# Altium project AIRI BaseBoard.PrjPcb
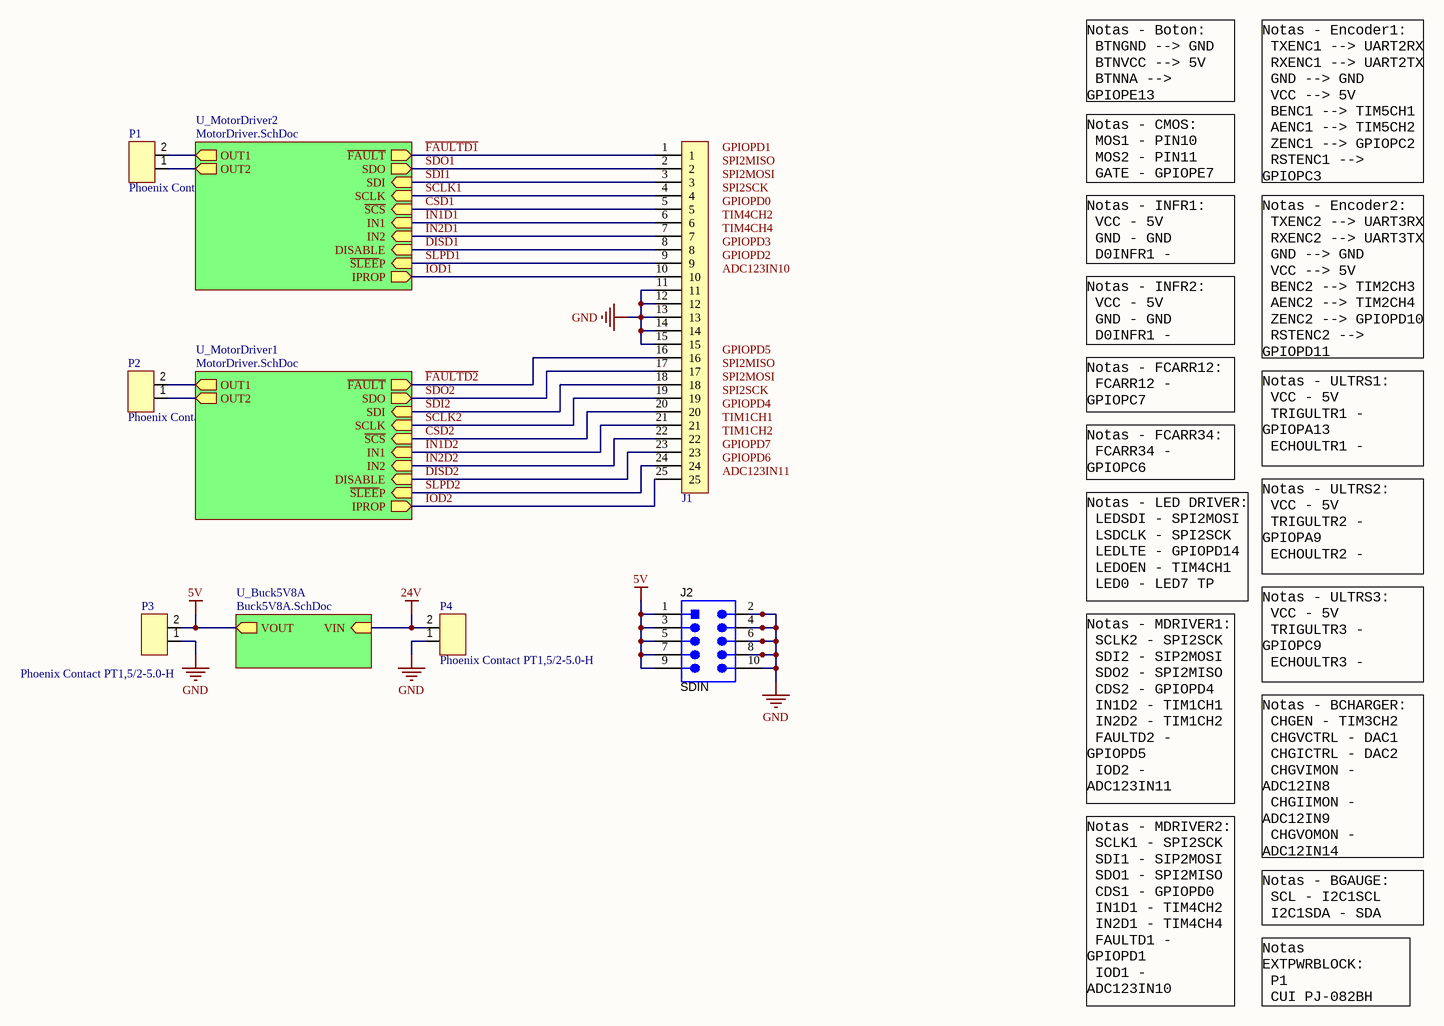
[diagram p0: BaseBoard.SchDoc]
3 sheets, 47 parts. Net scope: hierarchical (ports join the sheet entries above them; power ports are global).
Sheets:
  BaseBoard.SchDoc
    U_Buck5V8A = Buck5V8A.SchDoc
    U_MotorDriver2 = MotorDriver.SchDoc
    U_MotorDriver1 = MotorDriver.SchDoc

## Sheet BaseBoard.SchDoc
size A3; DocumentNumber: 1; SheetNumber: 1; SheetTotal: 9

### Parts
J1  Sullins PREC025SAAN-RC  [PCB-ss9uik38su1ryg1jck95-1]  (value not drawn)
J2  SDIN  [PCB-38ol6r0j9lzrfjjpfgyz-1]
P1  Phoenix Contact PT1,5/2-5.0-H  [PCB-uxxh2nr7ib8r5ep0eqej-1]
P2  Phoenix Contact PT1,5/2-5.0-H  [PCB-uxxh2nr7ib8r5ep0eqej-1]
P3  Phoenix Contact PT1,5/2-5.0-H  [PCB-uxxh2nr7ib8r5ep0eqej-1]
P4  Phoenix Contact PT1,5/2-5.0-H  [PCB-uxxh2nr7ib8r5ep0eqej-1]

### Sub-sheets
U_Buck5V8A = Buck5V8A.SchDoc: VOUT (out), VIN (in)
U_MotorDriver1 = MotorDriver.SchDoc: OUT1 (out), OUT2 (out), IPROP (out), SDO, ~{FAULT} (out), SDI (in), SCLK (in), ~{SCS} (in), ~{SLEE}P (in), DISABLE (in), IN2 (in), IN1 (in)
U_MotorDriver2 = MotorDriver.SchDoc: OUT1 (out), OUT2 (out), IPROP (out), SDO (out), ~{FAULT} (out), SDI (in), SCLK (in), ~{SCS} (in), ~{SLEE}P (in), DISABLE (in), IN2 (in), IN1 (in)

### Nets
5V: J2.1 J2.3 J2.5 J2.7 J2.9 P3.2 ; sheet U_Buck5V8A/VOUT
24V: P4.2 ; sheet U_Buck5V8A/VIN
GND: J1.11 J1.12 J1.13 J1.14 J1.15 J2.2 J2.4 J2.6 J2.8 J2.10 P3.1 P4.1
~{CSD1}: J1.5 ; sheet U_MotorDriver2/~{SCS}
~{CSD2}: J1.20 ; sheet U_MotorDriver1/~{SCS}
DISD1: J1.8 ; sheet U_MotorDriver2/DISABLE
DISD2: J1.23 ; sheet U_MotorDriver1/DISABLE
~{FAULTD1}: J1.1 ; sheet U_MotorDriver2/~{FAULT}
~{FAULTD2}: J1.16 ; sheet U_MotorDriver1/~{FAULT}
IN1D1: J1.6 ; sheet U_MotorDriver2/IN1
IN1D2: J1.21 ; sheet U_MotorDriver1/IN1
IN2D1: J1.7 ; sheet U_MotorDriver2/IN2
IN2D2: J1.22 ; sheet U_MotorDriver1/IN2
IOD1: J1.10 ; sheet U_MotorDriver2/IPROP
IOD2: J1.25 ; sheet U_MotorDriver1/IPROP
~{SLPD1}: J1.9 ; sheet U_MotorDriver2/~{SLEE}P
~{SLPD2}: J1.24 ; sheet U_MotorDriver1/~{SLEE}P
SCLK1: J1.4 ; sheet U_MotorDriver2/SCLK
SCLK2: J1.19 ; sheet U_MotorDriver1/SCLK
SDI1: J1.3 ; sheet U_MotorDriver2/SDI
SDI2: J1.18 ; sheet U_MotorDriver1/SDI
SDO1: J1.2 ; sheet U_MotorDriver2/SDO
SDO2: J1.17 ; sheet U_MotorDriver1/SDO
NetP1_1: P1.1 ; sheet U_MotorDriver2/OUT2
NetP1_2: P1.2 ; sheet U_MotorDriver2/OUT1
NetP2_1: P2.1 ; sheet U_MotorDriver1/OUT2
NetP2_2: P2.2 ; sheet U_MotorDriver1/OUT1

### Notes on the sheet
- Notas - Boton:
  BTNGND --> GND
  BTNVCC --> 5V
  BTNNA --> GPIOPE13
  BTNCMN --> 3.3V
- Notas - CMOS:
  MOS1 - PIN10
  MOS2 - PIN11
  GATE - GPIOPE7
- Notas - Encoder1:
  TXENC1 --> UART2RX
  RXENC1 --> UART2TX
  GND --> GND
  VCC --> 5V
  BENC1 --> TIM5CH1
  AENC1 --> TIM5CH2
  ZENC1 --> GPIOPC2
  RSTENC1 --> GPIOPC3
- Notas - INFR1:
  VCC - 5V
  GND - GND
  D0INFR1 - GPIOPA15
- Notas - INFR2:
  VCC - 5V
  GND - GND
  D0INFR1 - GPIOPA14
- Notas - Encoder2:
  TXENC2 --> UART3RX
  RXENC2 --> UART3TX
  GND --> GND
  VCC --> 5V
  BENC2 --> TIM2CH3
  AENC2 --> TIM2CH4
  ZENC2 --> GPIOPD10
  RSTENC2 --> GPIOPD11
- Notas - FCARR12:
  FCARR12 - GPIOPC7
  GND - GND
- Notas - ULTRS1:
  VCC - 5V
  TRIGULTR1 - GPIOPA13
  ECHOULTR1 - GPIOPA10
  GND - GND
- Notas - FCARR34:
  FCARR34 - GPIOPC6
  GND - GND
- Notas - LED DRIVER:
  LEDSDI - SPI2MOSI
  LSDCLK - SPI2SCK
  LEDLTE - GPIOPD14
  LEDOEN - TIM4CH1
  LED0 - LED7 TP
- Notas - ULTRS2:
  VCC - 5V
  TRIGULTR2 - GPIOPA9
  ECHOULTR2 - GPIOPA8
  GND - GND
- Notas - ULTRS3:
  VCC - 5V
  TRIGULTR3 - GPIOPC9
  ECHOULTR3 - GPIOPC8
  GND - GND
- Notas - MDRIVER1:
  SCLK2 - SPI2SCK
  SDI2 - SIP2MOSI
  SDO2 - SPI2MISO
  CDS2 - GPIOPD4
  IN1D2 - TIM1CH1
  IN2D2 - TIM1CH2
  FAULTD2 - GPIOPD5
  IOD2 - ADC123IN11
  SLPD2 - GPIOPD6
  DISD2 - GPIOPD7
- Notas - BCHARGER:
  CHGEN - TIM3CH2
  CHGVCTRL - DAC1
  CHGICTRL - DAC2
  CHGVIMON - ADC12IN8
  CHGIIMON - ADC12IN9
  CHGVOMON - ADC12IN14
  CHGIOMON - ADC12IN15
  CHGFAULT - GPIOPA6
- Notas - BGAUGE:
  SCL - I2C1SCL
  I2C1SDA - SDA
- Notas - MDRIVER2:
  SCLK1 - SPI2SCK
  SDI1 - SIP2MOSI
  SDO1 - SPI2MISO
  CDS1 - GPIOPD0
  IN1D1 - TIM4CH2
  IN2D1 - TIM4CH4
  FAULTD1 - GPIOPD1
  IOD1 - ADC123IN10
  SLPD1 - GPIOPD2
  DISD1 - GPIOPD3
- Notas EXTPWRBLOCK:
  P1
  CUI PJ-082BH
- Labels drawn without touching a wire or pin: ADC123IN10, ADC123IN11, GPIOPD0, GPIOPD1, GPIOPD2, GPIOPD3, GPIOPD4, GPIOPD5, GPIOPD6, GPIOPD7, SPI2MISO, SPI2MOSI, SPI2SCK, TIM1CH1, TIM1CH2, TIM4CH2, TIM4CH4

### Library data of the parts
J1 = CMP-10abd8f28bd1cf6c-1: Conn Header Vert 25POS 2.54MM
J2 = CMP-eeb327bddb303174-2: Male, 10C, Straight, .100CC; 5.84mm Head/3.05mm Tail, Gold; PBT Phos Bronze, 125 C; Manufacturer Part Number: PBC05DAAN; Number of Positions: 10; Pin Pitch: 2.54 mm
P1-P4 = CMP-29d3e01a948df614-2: TERM BLK, PCB, SCREW, 5.0MM, 2WAY; Connector Type: Terminal Block, PCB; Series: PT 1.5; Connector Mounting: PCB; Pitc...

## Sheet Buck5V8A.SchDoc
size A; DocumentNumber: 3; SheetNumber: 3; SheetTotal: 9
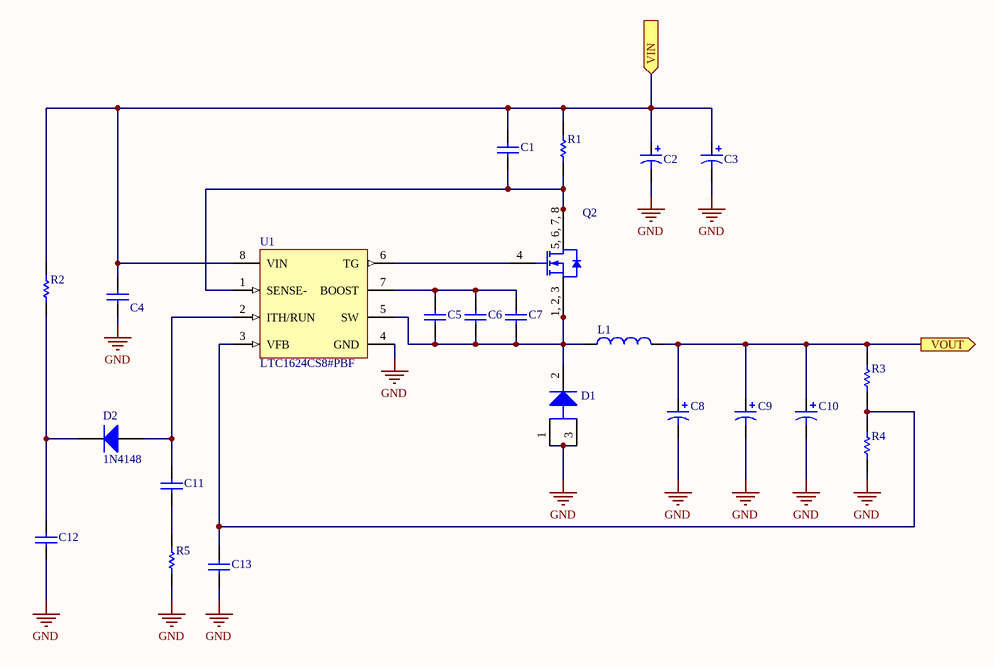
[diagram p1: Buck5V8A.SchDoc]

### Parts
C1  KEMET C0805C102J5HACAUTO  [C0805]  (value not drawn)
C2  Panasonic EEH-ZK1V331P  [Panasonic Series ZK Type V Size G]  (value not drawn)
C3  Panasonic EEH-ZK1V331P  [Panasonic Series ZK Type V Size G]  (value not drawn)
C4  Murata GCD21BR71H104KA01L  [PCB-ssva2zk340p4bh5zvq6f-1]  (value not drawn)
C5  Murata GCD21BR71H104KA01L  [PCB-ssva2zk340p4bh5zvq6f-1]  (value not drawn)
C6  Murata GCD21BR71H104KA01L  [PCB-ssva2zk340p4bh5zvq6f-1]  (value not drawn)
C7  Murata GCD21BR71H104KA01L  [PCB-ssva2zk340p4bh5zvq6f-1]  (value not drawn)
C8  Panasonic EEE-FT1C102AP  [PCB-xaiyb7r7dwp27xp9tfwa-1]  (value not drawn)
C9  Panasonic EEE-FT1C102AP  [PCB-xaiyb7r7dwp27xp9tfwa-1]  (value not drawn)
C10  Panasonic 16SVPE180M  [PCB-ae1oimqhkk0yeik3kf6i-1]  (value not drawn)
C11  KEMET C0805C102J5HACAUTO  [C0805]  (value not drawn)
C12  Murata GCM21BR71H104KA37L  [C0805]  (value not drawn)
C13  Kemet C0805C101J5GAC7800  [C0805]  (value not drawn)
D1  MBRB1645T4G  [HTD2PAK]  (value not drawn)
D2  1N4148  [SODFL250X100-2M]
L1  Bourns SRP1770C-470M  [SRP1770C]  (value not drawn)
Q2  Infineon IRF7470TRPBF  [SOIC8]  (value not drawn)
R1  Yageo PE1206FRF7W0R012L  [PF1206]  (value not drawn)
R2  Yageo RC0805FR-071ML  [PCB-lzr0fin07yxsgk684m62-1]  (value not drawn)
R3  Yageo RC0805FR-0718KL  [RESC2013X60X35ML10T20]  (value not drawn)
R4  Yageo RC0805FR-075K6L  [RC0805FR]  (value not drawn)
R5  Yageo RC0805FR-075K6L  [RC0805FR]  (value not drawn)
U1  LTC1624CS8#PBF  [LT-S8-8_L]

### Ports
VIN (in), VOUT (out)

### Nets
5V: C8.1 C9.1 C10.1 L1.2 R3.2 ; port VOUT
24V: C1.2 C2.1 C3.1 C4.1 R1.2 R2.2 U1.8(VIN) ; port VIN
GND: C2.2 C3.2 C4.2 C8.2 C9.2 C10.2 C12.1 C13.1 D1.1(A) D1.3(A) R4.1 R5.1 U1.4(GND)
NetC1_1: C1.1 Q2.5(D) Q2.6(D) Q2.7(D) Q2.8(D) R1.1 U1.1(SENSE-)
NetC5_1: C5.1 C6.2 C7.1 D1.2(K) L1.1 Q2.1(S) Q2.2(S) Q2.3(S) U1.5(SW)
NetC5_2: C5.2 C6.1 C7.2 U1.7(BOOST)
NetC11_1: C11.1 R5.2
NetC11_2: C11.2 D2.1(A) U1.2(ITH/RUN)
NetC12_2: C12.2 D2.2(K) R2.1
NetC13_2: C13.2 R3.1 R4.2 U1.3(VFB)
NetQ2_4: Q2.4(G) U1.6(TG)

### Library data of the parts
C1 C11 = CMP-4c3f800f43c993f8-1: Cap Ceramic 0.001uF 50V X8R 5% Pad SMD 0805 150C Automotive T/R; Capacitance: 1.00 nF; Lead-Free Status: Lead Free; Voltage Rating (DC): 50.0 V
C2 C3 = CMP-bfb3722bbd176074-3: EEH ZK (V) Series 35 V 330 uF 105°C 10x10.2 mm SMT Hybrid Aluminum Polymer
C4-C7 = CMP-5b5d9311dba3849a-1: Cap Ceramic 0.1uF 50V X7R 10% Pad SMD 0805 125C Automotive T/R; Capacitance: 100 nF; Voltage Rating (DC): 50.0 V
C8 C9 = CMP-36c9fe878397e90e-7: Cap Aluminum Lytic 1000uF 16V 20% (10.5 X 10.0mm) SMD 0.06 Ohm 1190mA 2000h 105?C Automotive T/R; Lead-Free Status: Lead Free; Voltage Rating (DC): 16.0 V; Equivalent Series Resistance (ESR): 60 mΩ; Capacitance: 1000 µF
C10 = CMP-11222308-5: Cap Aluminum 180uF 16V 20% (6.3 X 9.9mm) Cylindrical 4460mA 2000hr 105°C T/R; Voltage Rating (DC): 16.0 V; Equivalent Series Resistance (ESR): 0.011 Ω; Capacitance: 0.00018 F; Lead-Free Status: Lead Free
C12 = CMP-135114-3: Cap Ceramic 0.1uF 50V X7R 10% SMD 0805 125C Embossed T/R; Capacitance: 1e-07 F; Lead-Free Status: Lead Free; Voltage Rating (DC): 50.0 V
C13 = CMP-8262039-4: Multilayer Ceramic Capacitors MLCC - SMD/SMT 50volts 100pF C0G 5%; Manufacturer Part Number: C0805C101J5GACTU; Capacitance: 1e-10 F; Lead-Free Status: Lead Free; Voltage Rating (DC): 50.0 V
D1 = CMP-822676-10: SWITCHMODE(TM) Power Rectifier, 45 V, 3-Pin D2PAK, Pb-Free, Tube
D2 = CMP-814637-10: Small Signal Diode, 75 V, 0.15 A, -55 to 150 degC, 2-Pin SOD-323, RoHS, Tape and Reel
L1 = CMP-e4132b39041c3bd4-1: Inductor Power Shielded 47uH 20% 8.7A 7MHz 2-Pin Surface Mount T/R
Q2 = CMP-983352d49b9a47f4-3: Mosfet, Power; N-ch; Vdss 40V; Rds(on) 9 Milliohms; Id 10A; SO-8; Pd 2.5W; Vgs +/-12V; Current Rating: 11.0 A; Lead-Free Status: Lead Free; Voltage Rating (DC): 40.0 V; Breakdown Voltage (Drain to Source): 40.0 V (min); Drain to Source Resistance (on) (Rds): 9.00 m?; Polarity: N-Channel; Rise Time: 1.90 ns; Continuous Drain Current (Ids): 11.0 A, 10.0 A; Power Dissipation: 2.50 W
R1 = CMP-ed1a2051f20e32dd-1: Res Current Sense Metal Foil 1206 12m Ohms 1% 1/2W ±100ppm/°C Molded SMD Paper T/R; Resistance: 12.0 m?
R2 = CMP-c7f10c99c5f61836-7: Res Thick Film 0805 1M Ohm 1% 0.125W(1/8W) ±100ppm/C Pad SMD T/R; Case/Package (SI): 2012; Lead-Free Status: Lead Free; Power Rating: 125 mW; Resistance: 1.00 M?; Temperature Coefficient: -100 ppm/°C to 100 ppm/°C; Voltage Rating (DC): 150 V
R3 = CMP-1875592-5: YAGEO (PHYCOMP)   RC0805FR-0718KL   RESISTOR, RC12H 0805 18K; Resistance Tolerance: ±1%; Power Rating: 0.125 W; Lead-Free Status: Lead Free; Voltage Rating (DC): 150.0 V; Case/Package (SI): 2012; Resistance: 18000.0 Ω
R4 R5 = CMP-5c9997e7c49d835e-2: Res Thick Film 0805 5.6K Ohm 1% 0.125W(1/8W) ±100ppm/C Pad SMD T/R; Power Rating: 125 mW; Case/Package (SI): 2012; Voltage Rating (DC): 150 V; Resistance: 5.60 k?; Temperature Coefficient: -100 ppm/°C to 100 ppm/°C; Lead-Free Status: Lead Free
U1 = CMP-1475384-2: High Efficiency N-Channel Switching Regulator Controller, 8-pin SOIC (S8-8), 0 to 70 degC, Pb-Free; Frequency: 225000.0 Hz; Lead-Free Status: Lead Free; Number of Outputs: 1; Output Current: 10.0 A; Output Voltage: 30.0 V

## Sheet MotorDriver.SchDoc
size A; DocumentNumber: 4; SheetNumber: 4; SheetTotal: 9
Used 2 times, as channels U_MotorDriver2, U_MotorDriver1. Parts and nets are listed once, with the designators drawn on the sheet.
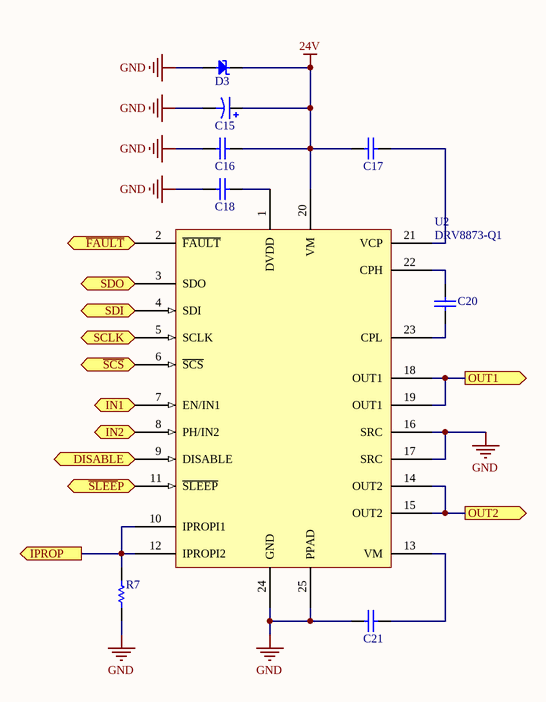
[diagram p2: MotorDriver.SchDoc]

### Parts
C15  Panasonic EEE-HA1V101XP  [PCB-yncmx9jt7av7ibwhpkx7-1]  (value not drawn)
C16  Murata GCD21BR71H104KA01L  [PCB-ssva2zk340p4bh5zvq6f-1]  (value not drawn)
C17  Murata GCM21BR71H105KA03L  [CAPC2013X140X45ML15T25]  (value not drawn)
C18  Murata GCM21BR71H105KA03L  [CAPC2013X140X45ML15T25]  (value not drawn)
C20  Murata GCE21BR71H473KA01L  [PCB-vdoll2pl29m8ltnc4a0p-1]  (value not drawn)
C21  Murata GCD21BR71H104KA01L  [PCB-ssva2zk340p4bh5zvq6f-1]  (value not drawn)
D3  SMBJ28A  [PCB-c143qqmc0v6vbhfo61i0-1]  (value not drawn)
R7  Yageo RC0805FR-07820RL  [PCB-tlec0rbgb5i2w1be04n0-1]  (value not drawn)
U2  DRV8873-Q1  [HTSSOP-24]

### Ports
DISABLE (in), IN1 (in), IN2 (in), IPROP (out), OUT1 (out), OUT2 (out), SCLK (in), SDI (in), SDO (out), ~{FAULT} (out), ~{SCS} (in), ~{SLEE}P (in)

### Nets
24V: C15.1 C16.1 C17.2 D3.1(K) U2.20(VM)
GND: C15.2 C16.2 C18.2 C21.2 D3.2(A) R7.1 U2.16(SRC) U2.17(SRC) U2.24(GND) U2.25(PPAD)
DISABLE: U2.9(DISABLE) ; port DISABLE
~{FAULT}: U2.2(~{FAULT}) ; port ~{FAULT}
IN1: U2.7(EN/IN1) ; port IN1
IN2: U2.8(PH/IN2) ; port IN2
IPROP: R7.2 U2.10(IPROPI1) U2.12(IPROPI2) ; port IPROP
OUT1: U2.18(OUT1) U2.19(OUT1) ; port OUT1
OUT2: U2.14(OUT2) U2.15(OUT2) ; port OUT2
~{SCS}: U2.6(~{SCS}) ; port ~{SCS}
~{SLEE}P: U2.11(~{SLEEP}) ; port ~{SLEE}P
SCLK: U2.5(SCLK) ; port SCLK
SDI: U2.4(SDI) ; port SDI
SDO: U2.3(SDO) ; port SDO
NetC17_1: C17.1 U2.21(VCP)
NetC18_1: C18.1 U2.1(DVDD)
NetC20_1: C20.1 U2.23(CPL)
NetC20_2: C20.2 U2.22(CPH)
NetC21_1: C21.1 U2.13(VM)

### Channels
U_MotorDriver2: designators end in _$ChannelName#1; ports DISABLE=DISD1 IN1=IN1D1 IN2=IN2D1 IPROP=IOD1 OUT1=NetP1_2 OUT2=NetP1_1 SCLK=SCLK1 SDI=SDI1 SDO=SDO1 ~{FAULT}=~{FAULTD1} ~{SCS}=~{CSD1} ~{SLEE}P=~{SLPD1}
U_MotorDriver1: designators end in _$ChannelName#2; ports DISABLE=DISD2 IN1=IN1D2 IN2=IN2D2 IPROP=IOD2 OUT1=NetP2_2 OUT2=NetP2_1 SCLK=SCLK2 SDI=SDI2 SDO=SDO2 ~{FAULT}=~{FAULTD2} ~{SCS}=~{CSD2} ~{SLEE}P=~{SLPD2}

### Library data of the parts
C15 = CMP-2d6fe63f67daf2a8-1: Electrolytic capacitor SMD 100 µF 35 V 20 % (Ø) 6.3 mm Panasonic EEE-HA1V101XP 1 pc(s); Lead-Free Status: Lead Free
C16 C21 = CMP-5b5d9311dba3849a-1: as C4 on sheet Buck5V8A
C17 C18 = CMP-9133247-2: Cap Ceramic 1uF 50V X7R 10% SMD 0805 125C Embossed T/R; Capacitance: 1e-06 F; Lead-Free Status: Lead Free; Voltage Rating (DC): 50.0 V
C20 = CMP-0103c9dfcdd1dec4-1: Cap Ceramic 0.047uF 50V X7R 10% SMD 0805 125°C Embossed Plastic T/R
D3 = CMP-ea40234f95603587-2: Transient Voltage Suppressor, TVS, SMBJ Series, Unidirectional, 28 V, DO-214AA, 2, 31.1 V; Operating Voltage: 28.0 V; Power Rating: 600 W
R7 = CMP-d46c1f1e7e700bab-2: Surface Mount Thick Film Resistor, RC Series, 820 ohm, 125 mW, - 1%, 150 V, 0805 [2012 Metric]; Lead-Free Status: Lead Free; Case/Package (SI): 2012; Power Rating: 125 mW; Resistance: 820 ?; Voltage Rating (DC): 150 V
U2 = CMP-9df0515b45cc4237-8: Automotive H-bridge motor driver with integrated current sensing and current sense output 24-HTSSOP -40 to 125

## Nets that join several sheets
5V: BaseBoard (6 pins), Buck5V8A (5 pins)
24V: BaseBoard (P4.2), Buck5V8A (7 pins), U_MotorDriver2 (5 pins), U_MotorDriver1 (5 pins)
GND: BaseBoard (12 pins), Buck5V8A (13 pins), U_MotorDriver2 (10 pins), U_MotorDriver1 (10 pins)
~{CSD1}: BaseBoard (J1.5), U_MotorDriver2 (U2_$ChannelName#1.6)
~{CSD2}: BaseBoard (J1.20), U_MotorDriver1 (U2_$ChannelName#2.6)
DISD1: BaseBoard (J1.8), U_MotorDriver2 (U2_$ChannelName#1.9)
DISD2: BaseBoard (J1.23), U_MotorDriver1 (U2_$ChannelName#2.9)
~{FAULTD1}: BaseBoard (J1.1), U_MotorDriver2 (U2_$ChannelName#1.2)
~{FAULTD2}: BaseBoard (J1.16), U_MotorDriver1 (U2_$ChannelName#2.2)
IN1D1: BaseBoard (J1.6), U_MotorDriver2 (U2_$ChannelName#1.7)
IN1D2: BaseBoard (J1.21), U_MotorDriver1 (U2_$ChannelName#2.7)
IN2D1: BaseBoard (J1.7), U_MotorDriver2 (U2_$ChannelName#1.8)
IN2D2: BaseBoard (J1.22), U_MotorDriver1 (U2_$ChannelName#2.8)
IOD1: BaseBoard (J1.10), U_MotorDriver2 (R7_$ChannelName#1.2 U2_$ChannelName#1.10 U2_$ChannelName#1.12)
IOD2: BaseBoard (J1.25), U_MotorDriver1 (R7_$ChannelName#2.2 U2_$ChannelName#2.10 U2_$ChannelName#2.12)
NetP1_1: BaseBoard (P1.1), U_MotorDriver2 (U2_$ChannelName#1.14 U2_$ChannelName#1.15)
NetP1_2: BaseBoard (P1.2), U_MotorDriver2 (U2_$ChannelName#1.18 U2_$ChannelName#1.19)
NetP2_1: BaseBoard (P2.1), U_MotorDriver1 (U2_$ChannelName#2.14 U2_$ChannelName#2.15)
NetP2_2: BaseBoard (P2.2), U_MotorDriver1 (U2_$ChannelName#2.18 U2_$ChannelName#2.19)
~{SLPD1}: BaseBoard (J1.9), U_MotorDriver2 (U2_$ChannelName#1.11)
~{SLPD2}: BaseBoard (J1.24), U_MotorDriver1 (U2_$ChannelName#2.11)
SCLK1: BaseBoard (J1.4), U_MotorDriver2 (U2_$ChannelName#1.5)
SCLK2: BaseBoard (J1.19), U_MotorDriver1 (U2_$ChannelName#2.5)
SDI1: BaseBoard (J1.3), U_MotorDriver2 (U2_$ChannelName#1.4)
SDI2: BaseBoard (J1.18), U_MotorDriver1 (U2_$ChannelName#2.4)
SDO1: BaseBoard (J1.2), U_MotorDriver2 (U2_$ChannelName#1.3)
SDO2: BaseBoard (J1.17), U_MotorDriver1 (U2_$ChannelName#2.3)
